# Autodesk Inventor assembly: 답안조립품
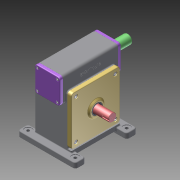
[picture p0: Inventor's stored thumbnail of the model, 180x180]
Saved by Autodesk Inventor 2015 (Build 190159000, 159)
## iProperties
Created: 2025-06
Part Number: 답안조립품
Document SubType Name: Assembly
Designer: User
Author: User
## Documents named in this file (13)
- C:\Users\User\Desktop\750603V1003\답안조립품.iam
- C:\Users\User\Documents\Inventor\6각 구멍붙이 볼트 M6x12.ipt
- C:\Users\User\Desktop\750603V1003\가져온 구성요소\6각 구멍붙이 볼트 M8x20\6각 구멍붙이 볼트 M8x20.ipt
- C:\Users\User\Desktop\750603V1003\가져온 구성요소\깊은 홈 볼 베어링 6206\깊은 홈 볼 베어링 6206.ipt
- C:\Users\User\Desktop\750603V1003\가져온 구성요소\깊은 홈 볼 베어링 6209\깊은 홈 볼 베어링 6209.ipt
- C:\Users\User\Desktop\750603V1003\가져온 구성요소\뒷커버\뒷커버.ipt
- C:\Users\User\Desktop\750603V1003\본체.ipt
- C:\Users\User\Desktop\750603V1003\가져온 구성요소\앞커버\앞커버.ipt
- C:\Users\User\Desktop\750603V1003\가져온 구성요소\오일 실 30 42 7\오일 실 30 42 7.ipt
- C:\Users\User\Desktop\750603V1003\가져온 구성요소\오일 실 35 55 11\오일 실 35 55 11.ipt
- C:\Users\User\Desktop\750603V1003\가져온 구성요소\웜 샤프트\웜 샤프트.ipt
- C:\Users\User\Desktop\750603V1003\가져온 구성요소\웜 휠 커버\웜 휠 커버.ipt
- C:\Users\User\Desktop\750603V1003\가져온 구성요소\웜 휠\웜 휠.ipt
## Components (12 placed, 2 different names)
1. 6각 구멍붙이 볼트 M6x12:1
2. 6각 구멍붙이 볼트 M6x12:2
3. 6각 구멍붙이 볼트 M6x12:3
4. 6각 구멍붙이 볼트 M6x12:4
5. 6각 구멍붙이 볼트 M6x12:5
6. 6각 구멍붙이 볼트 M6x12:6
7. 6각 구멍붙이 볼트 M6x12:7
8. 6각 구멍붙이 볼트 M6x12:8
9. 6각 구멍붙이 볼트 M8x20:1
10. 6각 구멍붙이 볼트 M8x20:2
11. 6각 구멍붙이 볼트 M8x20:3
12. 6각 구멍붙이 볼트 M8x20:4
